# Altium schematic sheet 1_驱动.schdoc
size 604 x 431 mm; Symbol: Sheet-Symbol_A2; Device: Sheet-Symbol_A2; Company: 嘉立创EDA; Version: V1.0; Page Size: A2; @Project Name: 辉光管时钟成品; @Page Count: 2; @Update Date: 2024-01-22; @Create Date: 2024-01-20; @Schematic Name: 驱动+控制部分; @Page No: 1; @Page Name: 驱动
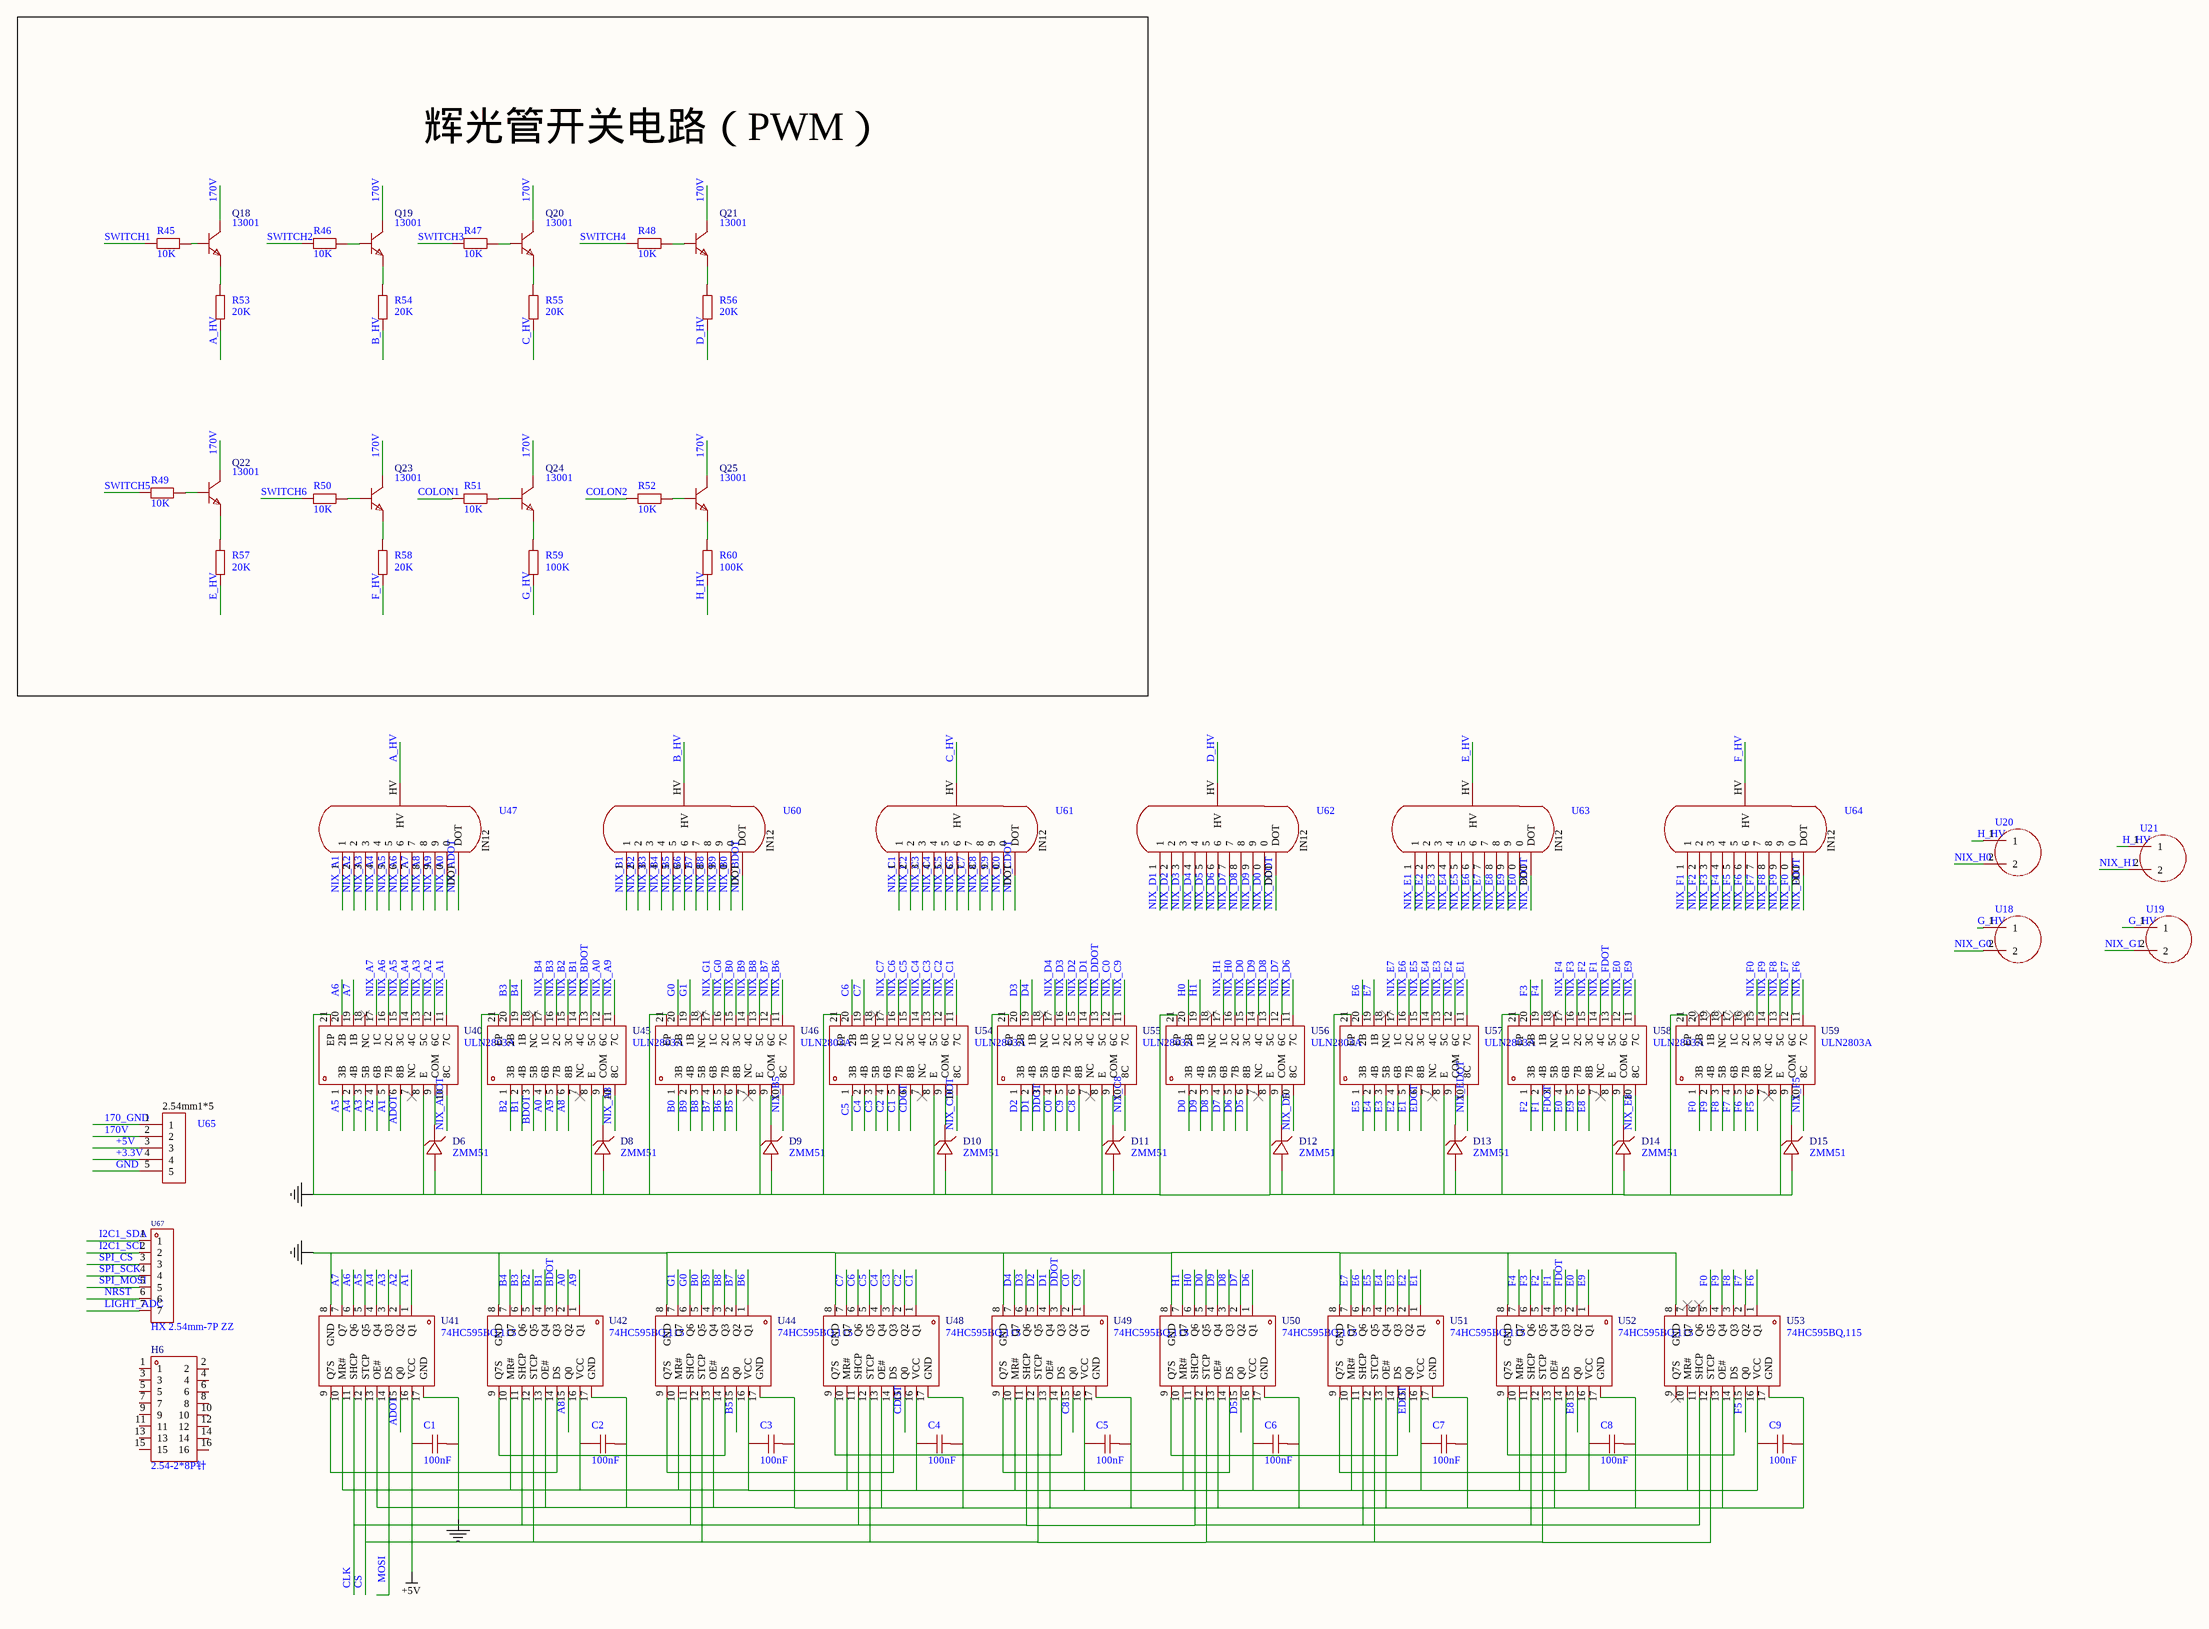
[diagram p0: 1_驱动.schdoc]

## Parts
C1  100nF  [C0603]
C2  100nF  [C0603]
C3  100nF  [C0603]
C4  100nF  [C0603]
C5  100nF  [C0603]
C6  100nF  [C0603]
C7  100nF  [C0603]
C8  100nF  [C0603]
C9  100nF  [C0603]
D6  ZMM51  [LL-34_L3.5-W1.5-RD]
D8  ZMM51  [LL-34_L3.5-W1.5-RD]
D9  ZMM51  [LL-34_L3.5-W1.5-RD]
D10  ZMM51  [LL-34_L3.5-W1.5-RD]
D11  ZMM51  [LL-34_L3.5-W1.5-RD]
D12  ZMM51  [LL-34_L3.5-W1.5-RD]
D13  ZMM51  [LL-34_L3.5-W1.5-RD]
D14  ZMM51  [LL-34_L3.5-W1.5-RD]
D15  ZMM51  [LL-34_L3.5-W1.5-RD]
H6  2.54-2*8P针  [HDR-TH_16P-P2.54-V-M-R2-C8-S2.54]
Q18  13001  [SOT-23-3_L2.9-W1.3-P1.90-LS2.4-BR]
Q19  13001  [SOT-23-3_L2.9-W1.3-P1.90-LS2.4-BR]
Q20  13001  [SOT-23-3_L2.9-W1.3-P1.90-LS2.4-BR]
Q21  13001  [SOT-23-3_L2.9-W1.3-P1.90-LS2.4-BR]
Q22  13001  [SOT-23-3_L2.9-W1.3-P1.90-LS2.4-BR]
Q23  13001  [SOT-23-3_L2.9-W1.3-P1.90-LS2.4-BR]
Q24  13001  [SOT-23-3_L2.9-W1.3-P1.90-LS2.4-BR]
Q25  13001  [SOT-23-3_L2.9-W1.3-P1.90-LS2.4-BR]
R45  10K  [R0603]
R46  10K  [R0603]
R47  10K  [R0603]
R48  10K  [R0603]
R49  10K  [R0603]
R50  10K  [R0603]
R51  10K  [R0603]
R52  10K  [R0603]
R53  20K  [R0603]
R54  20K  [R0603]
R55  20K  [R0603]
R56  20K  [R0603]
R57  20K  [R0603]
R58  20K  [R0603]
R59  100K  [R0603]
R60  100K  [R0603]
U18  (no value)  [6*13氖泡]
U19  (no value)  [6*13氖泡]
U20  (no value)  [6*13氖泡]
U21  (no value)  [6*13氖泡]
U40  ULN2803A  [QFN-20_L4.0-W4.0-P0.50-BL-EP]
U41  74HC595BQ,115  [DHVQFN-16_L3.5-W2.5-P0.50-BL-EP]
U42  74HC595BQ,115  [DHVQFN-16_L3.5-W2.5-P0.50-BL-EP]
U44  74HC595BQ,115  [DHVQFN-16_L3.5-W2.5-P0.50-BL-EP]
U45  ULN2803A  [QFN-20_L4.0-W4.0-P0.50-BL-EP]
U46  ULN2803A  [QFN-20_L4.0-W4.0-P0.50-BL-EP]
U47  (no value)  [IN12]
U48  74HC595BQ,115  [DHVQFN-16_L3.5-W2.5-P0.50-BL-EP]
U49  74HC595BQ,115  [DHVQFN-16_L3.5-W2.5-P0.50-BL-EP]
U50  74HC595BQ,115  [DHVQFN-16_L3.5-W2.5-P0.50-BL-EP]
U51  74HC595BQ,115  [DHVQFN-16_L3.5-W2.5-P0.50-BL-EP]
U52  74HC595BQ,115  [DHVQFN-16_L3.5-W2.5-P0.50-BL-EP]
U53  74HC595BQ,115  [DHVQFN-16_L3.5-W2.5-P0.50-BL-EP]
U54  ULN2803A  [QFN-20_L4.0-W4.0-P0.50-BL-EP]
U55  ULN2803A  [QFN-20_L4.0-W4.0-P0.50-BL-EP]
U56  ULN2803A  [QFN-20_L4.0-W4.0-P0.50-BL-EP]
U57  ULN2803A  [QFN-20_L4.0-W4.0-P0.50-BL-EP]
U58  ULN2803A  [QFN-20_L4.0-W4.0-P0.50-BL-EP]
U59  ULN2803A  [QFN-20_L4.0-W4.0-P0.50-BL-EP]
U60  (no value)  [IN12]
U61  (no value)  [IN12]
U62  (no value)  [IN12]
U63  (no value)  [IN12]
U64  (no value)  [IN12]
U65  (no value)  [2.54mm1*5]
U67  HX 2.54mm-7P ZZ  [CONN-TH_7P-P2.50_HX-2.54MM-7P-ZZ]

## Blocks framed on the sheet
辉光管开关电路（PWM）: Q18-Q25 R45-R60

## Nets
170_GND: D6.2(A) D8.2(A) D9.2(A) D10.2(A) D11.2(A) D12.2(A) D13.2(A) D14.2(A) D15.2(A) U40.8(E) U40.21(EP) U45.8(E) U45.21(EP) U46.8(E) U46.21(EP) U54.8(E) U54.21(EP) U55.8(E) U55.21(EP) U56.8(E) U56.21(EP) U57.8(E) U57.21(EP) U58.8(E) U58.21(EP) U59.8(E) U59.21(EP) U65.1
+5V: C1.1 C2.1 C3.1 C4.1 C5.1 C6.1 C7.1 C8.1 C9.1 U41.10(MR#) U41.16(VCC) U42.10(MR#) U42.16(VCC) U44.10(MR#) U44.16(VCC) U48.10(MR#) U48.16(VCC) U49.10(MR#) U49.16(VCC) U50.10(MR#) U50.16(VCC) U51.10(MR#) U51.16(VCC) U52.10(MR#) U52.16(VCC) U53.10(MR#) U53.16(VCC) U65.3
GND: C1.2 C2.2 C3.2 C4.2 C5.2 C6.2 C7.2 C8.2 C9.2 U41.8(GND) U41.13(OE#) U41.17(GND) U42.8(GND) U42.13(OE#) U42.17(GND) U44.8(GND) U44.13(OE#) U44.17(GND) U48.8(GND) U48.13(OE#) U48.17(GND) U49.8(GND) U49.13(OE#) U49.17(GND) U50.8(GND) U50.13(OE#) U50.17(GND) U51.8(GND) U51.13(OE#) U51.17(GND) U52.8(GND) U52.13(OE#) U52.17(GND) U53.8(GND) U53.13(OE#) U53.17(GND) U65.5
170V: Q18.3(C) Q19.3(C) Q20.3(C) Q21.3(C) Q22.3(C) Q23.3(C) Q24.3(C) Q25.3(C) U65.2
+3.3V: U65.4
A0: U42.2(Q2) U45.4(6B)
A1: U40.5(7B) U41.1(Q1)
A2: U40.4(6B) U41.2(Q2)
A3: U40.3(5B) U41.3(Q3)
A4: U40.2(4B) U41.4(Q4)
A5: U40.1(3B) U41.5(Q5)
A6: U40.20(2B) U41.6(Q6)
A7: U40.19(1B) U41.7(Q7)
A8: U42.15(Q0) U45.6(8B)
A9: U42.1(Q1) U45.5(7B)
A_HV: R53.1 U47.HV
ADOT: U40.6(8B) U41.15(Q0)
B0: U44.5(Q5) U46.1(3B)
B1: U42.4(Q4) U45.2(4B)
B2: U42.5(Q5) U45.1(3B)
B3: U42.6(Q6) U45.20(2B)
B4: U42.7(Q7) U45.19(1B)
B5: U44.15(Q0) U46.6(8B)
B6: U44.1(Q1) U46.5(7B)
B7: U44.2(Q2) U46.4(6B)
B8: U44.3(Q3) U46.3(5B)
B9: U44.4(Q4) U46.2(4B)
B_HV: R54.1 U60.HV
BDOT: U42.3(Q3) U45.3(5B)
C0: U49.2(Q2) U55.4(6B)
C1: U48.1(Q1) U54.5(7B)
C2: U48.2(Q2) U54.4(6B)
C3: U48.3(Q3) U54.3(5B)
C4: U48.4(Q4) U54.2(4B)
C5: U48.5(Q5) U54.1(3B)
C6: U48.6(Q6) U54.20(2B)
C7: U48.7(Q7) U54.19(1B)
C8: U49.15(Q0) U55.6(8B)
C9: U49.1(Q1) U55.5(7B)
C_HV: R55.1 U61.HV
CDOT: U48.15(Q0) U54.6(8B)
CLK: U41.11(SHCP) U42.11(SHCP) U44.11(SHCP) U48.11(SHCP) U49.11(SHCP) U50.11(SHCP) U51.11(SHCP) U52.11(SHCP) U53.11(SHCP)
COLON1: R51.1
COLON2: R52.1
CS: U41.12(STCP) U42.12(STCP) U44.12(STCP) U48.12(STCP) U49.12(STCP) U50.12(STCP) U51.12(STCP) U52.12(STCP) U53.12(STCP)
D0: U50.5(Q5) U56.1(3B)
D1: U49.4(Q4) U55.2(4B)
D2: U49.5(Q5) U55.1(3B)
D3: U49.6(Q6) U55.20(2B)
D4: U49.7(Q7) U55.19(1B)
D5: U50.15(Q0) U56.6(8B)
D6: U50.1(Q1) U56.5(7B)
D7: U50.2(Q2) U56.4(6B)
D8: U50.3(Q3) U56.3(5B)
D9: U50.4(Q4) U56.2(4B)
D_HV: R56.1 U62.HV
DDOT: U49.3(Q3) U55.3(5B)
E0: U52.2(Q2) U58.4(6B)
E1: U51.1(Q1) U57.5(7B)
E2: U51.2(Q2) U57.4(6B)
E3: U51.3(Q3) U57.3(5B)
E4: U51.4(Q4) U57.2(4B)
E5: U51.5(Q5) U57.1(3B)
E6: U51.6(Q6) U57.20(2B)
E7: U51.7(Q7) U57.19(1B)
E8: U52.15(Q0) U58.6(8B)
E9: U52.1(Q1) U58.5(7B)
E_HV: R57.1 U63.HV
EDOT: U51.15(Q0) U57.6(8B)
F0: U53.5(Q5) U59.1(3B)
F1: U52.4(Q4) U58.2(4B)
F2: U52.5(Q5) U58.1(3B)
F3: U52.6(Q6) U58.20(2B)
F4: U52.7(Q7) U58.19(1B)
F5: U53.15(Q0) U59.6(8B)
F6: U53.1(Q1) U59.5(7B)
F7: U53.2(Q2) U59.4(6B)
F8: U53.3(Q3) U59.3(5B)
F9: U53.4(Q4) U59.2(4B)
F_HV: R58.1 U64.HV
FDOT: U52.3(Q3) U58.3(5B)
G0: U44.6(Q6) U46.20(2B)
G1: U44.7(Q7) U46.19(1B)
G_HV: R59.1 U18.1 U19.1
H0: U50.6(Q6) U56.20(2B)
H1: U50.7(Q7) U56.19(1B)
H_HV: R60.1 U20.1 U21.1
I2C1_SCL: U67.2
I2C1_SDA: U67.1
LIGHT_ADC: U67.7
MOSI: U41.14(DS)
NIX_A0: U45.12(6C) U47.0
NIX_A1: U40.11(7C) U47.1
NIX_A2: U40.12(6C) U47.2
NIX_A3: U40.13(5C) U47.3
NIX_A4: U40.14(4C) U47.4
NIX_A5: U40.15(3C) U47.5
NIX_A6: U40.16(2C) U47.6
NIX_A7: U40.17(1C) U47.7
NIX_A8: U45.10(8C) U47.8
NIX_A9: U45.11(7C) U47.9
NIX_ADOT: U40.10(8C) U47.DOT
NIX_B0: U46.15(3C) U60.0
NIX_B1: U45.14(4C) U60.1
NIX_B2: U45.15(3C) U60.2
NIX_B3: U45.16(2C) U60.3
NIX_B4: U45.17(1C) U60.4
NIX_B5: U46.10(8C) U60.5
NIX_B6: U46.11(7C) U60.6
NIX_B7: U46.12(6C) U60.7
NIX_B8: U46.13(5C) U60.8
NIX_B9: U46.14(4C) U60.9
NIX_BDOT: U45.13(5C) U60.DOT
NIX_C0: U55.12(6C) U61.0
NIX_C1: U54.11(7C) U61.1
NIX_C2: U54.12(6C) U61.2
NIX_C3: U54.13(5C) U61.3
NIX_C4: U54.14(4C) U61.4
NIX_C5: U54.15(3C) U61.5
NIX_C6: U54.16(2C) U61.6
NIX_C7: U54.17(1C) U61.7
NIX_C8: U55.10(8C) U61.8
NIX_C9: U55.11(7C) U61.9
NIX_CDOT: U54.10(8C) U61.DOT
NIX_D0: U56.15(3C) U62.0
NIX_D1: U55.14(4C) U62.1
NIX_D2: U55.15(3C) U62.2
NIX_D3: U55.16(2C) U62.3
NIX_D4: U55.17(1C) U62.4
NIX_D5: U56.10(8C) U62.5
NIX_D6: U56.11(7C) U62.6
NIX_D7: U56.12(6C) U62.7
NIX_D8: U56.13(5C) U62.8
NIX_D9: U56.14(4C) U62.9
NIX_DDOT: U55.13(5C) U62.DOT
NIX_E0: U58.12(6C) U63.0
NIX_E1: U57.11(7C) U63.1
NIX_E2: U57.12(6C) U63.2
NIX_E3: U57.13(5C) U63.3
NIX_E4: U57.14(4C) U63.4
NIX_E5: U57.15(3C) U63.5
NIX_E6: U57.16(2C) U63.6
NIX_E7: U57.17(1C) U63.7
NIX_E8: U58.10(8C) U63.8
NIX_E9: U58.11(7C) U63.9
NIX_EDOT: U57.10(8C) U63.DOT
NIX_F0: U59.15(3C) U64.0
NIX_F1: U58.14(4C) U64.1
NIX_F2: U58.15(3C) U64.2
NIX_F3: U58.16(2C) U64.3
NIX_F4: U58.17(1C) U64.4
NIX_F5: U59.10(8C) U64.5
NIX_F6: U59.11(7C) U64.6
NIX_F7: U59.12(6C) U64.7
NIX_F8: U59.13(5C) U64.8
NIX_F9: U59.14(4C) U64.9
NIX_FDOT: U58.13(5C) U64.DOT
NIX_G0: U18.2 U46.16(2C)
NIX_G1: U19.2 U46.17(1C)
NIX_H0: U20.2 U56.16(2C)
NIX_H1: U21.2 U56.17(1C)
NRST: U67.6
SPI_CS: U67.3
SPI_MOSI: U67.5
SPI_SCK: U67.4
SWITCH1: R45.1
SWITCH2: R46.1
SWITCH3: R47.1
SWITCH4: R48.1
SWITCH5: R49.1
SWITCH6: R50.1
NetD6_1: D6.1(C) U40.9(COM)
NetD8_1: D8.1(C) U45.9(COM)
NetD9_1: D9.1(C) U46.9(COM)
NetD10_1: D10.1(C) U54.9(COM)
NetD11_1: D11.1(C) U55.9(COM)
NetD12_1: D12.1(C) U56.9(COM)
NetD13_1: D13.1(C) U57.9(COM)
NetD14_1: D14.1(C) U58.9(COM)
NetD15_1: D15.1(C) U59.9(COM)
NetQ18_1: Q18.1(B) R45.2
NetQ18_2: Q18.2(E) R53.2
NetQ19_1: Q19.1(B) R46.2
NetQ19_2: Q19.2(E) R54.2
NetQ20_1: Q20.1(B) R47.2
NetQ20_2: Q20.2(E) R55.2
NetQ21_1: Q21.1(B) R48.2
NetQ21_2: Q21.2(E) R56.2
NetQ22_1: Q22.1(B) R49.2
NetQ22_2: Q22.2(E) R57.2
NetQ23_1: Q23.1(B) R50.2
NetQ23_2: Q23.2(E) R58.2
NetQ24_1: Q24.1(B) R51.2
NetQ24_2: Q24.2(E) R59.2
NetQ25_1: Q25.1(B) R52.2
NetQ25_2: Q25.2(E) R60.2
NetU41_9: U41.9(Q7S) U42.14(DS)
NetU42_9: U42.9(Q7S) U44.14(DS)
NetU44_9: U44.9(Q7S) U48.14(DS)
NetU48_9: U48.9(Q7S) U49.14(DS)
NetU49_9: U49.9(Q7S) U50.14(DS)
NetU50_9: U50.9(Q7S) U51.14(DS)
NetU51_9: U51.9(Q7S) U52.14(DS)
NetU52_9: U52.9(Q7S) U53.14(DS)

Not connected (* = marked no-connect by the designer): H6 1 2 3 4 5 6 7 8 9 10 11 12 13 14 15 16; U40 7(NC)* 18(NC)*; U45 7(NC)* 18(NC)*; U46 7(NC)* 18(NC)*; U53 6(Q6)* 7(Q7)* 9(Q7S)*; U54 7(NC)* 18(NC)*; U55 7(NC)* 18(NC)*; U56 7(NC)* 18(NC)*; U57 7(NC)* 18(NC)*; U58 7(NC)* 18(NC)*; U59 7(NC)* 16(2C)* 17(1C)* 18(NC)* 19(1B)* 20(2B)*

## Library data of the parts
C1-C9 = CAP_0603: Symbol: CapAcitance; Convert to PCB: yes
D6 D8-D15 = ZMM51: Manufacturer: ST(先科); Add into BOM: yes; Diode Configuration: 独立式; Zener Voltage (Nom): 51V; Reverse Leakage Current (Ir): 100nA@39V; Zener Voltage (Range): 48V~54V; Power Dissipation: 500mW; Zener Impedance (Zzt): 125Ω
H6 = 2.54-2*8P针_C779499: Manufacturer: BOOMELE(博穆精密); Add into BOM: yes
Q18-Q25 = 13001_C2904842: Manufacturer: YONGYUTAI(永裕泰); Add into BOM: yes; Transistor Type: NPN; Collector Current (Ic): 200mA; Collector-Emitter Breakdown Voltage (Vceo): 450V; Power Dissipation (Pd): 625mW; Transition Frequency (fT): 8MHz; Collector Cut-Off Current (Icbo): 100uA; Collector-Emitter Saturation Voltage (VCE(sat)@Ic,Ib): 400mV@50mA,10mA
R45-R60 = Res_0603: Symbol: 电阻; Convert to PCB: yes
U18-U21 = 氖泡: Add into BOM: yes
U40 U45 U46 U54-U59 = ULN2803A_C493377: Manufacturer: Mixic(中科芯亿达); Add into BOM: yes
U41 U42 U44 U48-U53 = 74HC595BQ,115: Manufacturer: Nexperia(安世); Add into BOM: yes
U47 U60-U64 = IN12: Add into BOM: yes
U65 = 2.54mm1*5: Add into BOM: yes
U67 = HX 2.54mm-7P ZZ: Manufacturer: hanxia(韩下); Symbol: HX 2.54MM-7P ZZ_C7543436; Add into BOM: yes; Pins Structure: 1x7P; Pitch: 2.5mm; Reference Series: XH; Number of PINs Per Row: 7; Current Rating (Max): 3A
